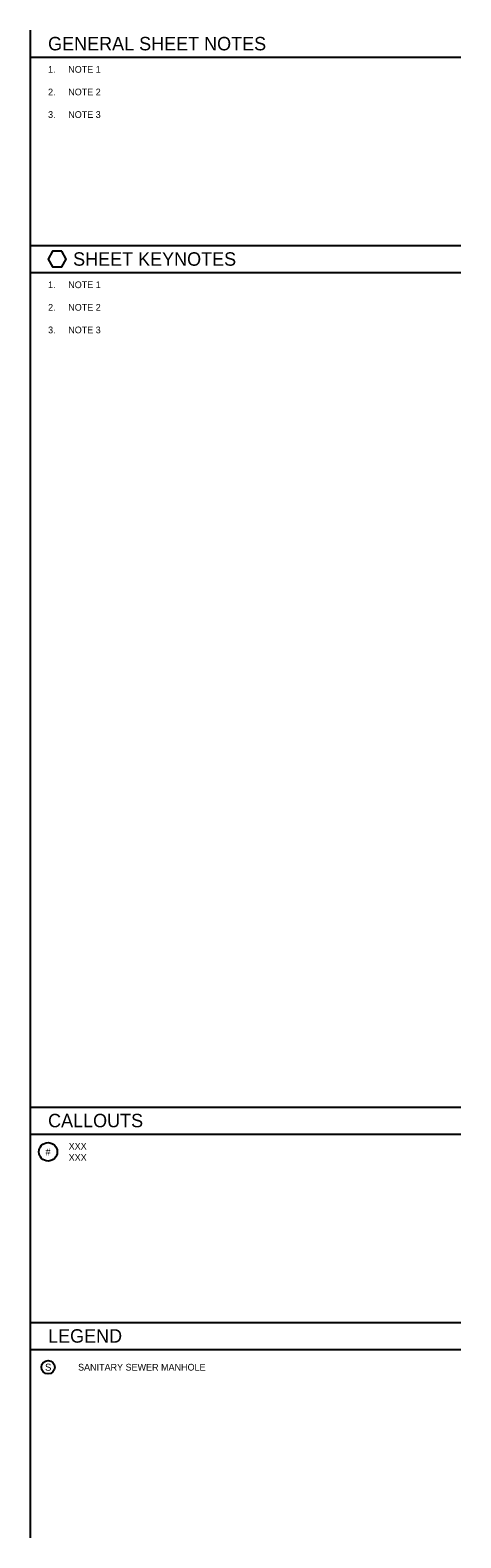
# Model space of a CAD drawing. Extents: x 2.11 to 2.61, y 0.03 to 1.78.
import ezdxf

# ---------------------------------------------------------------- set-up
doc = ezdxf.new("R2010")
doc.units = 0
for name, color, linetype in [('G-ANNO-KEYN', 7, 'Continuous'), ('G-ANNO-SYMB', 7, 'Continuous'), ('G-ANNO-TEXT', 7, 'Continuous'), ('G-DETL-GRPH', 7, 'Continuous')]:
    doc.layers.add(name, color=color, linetype=linetype)

msp = doc.modelspace()

# ---------------------------------------------------------------- linework, layer by layer
at = {"layer": 'G-ANNO-KEYN'}
msp.add_lwpolyline([(2.1512, 1.5273), (2.1407, 1.5273), (2.1354, 1.5182), (2.1407, 1.5091), (2.1512, 1.5091), (2.1565, 1.5182)], close=True, dxfattribs=at)
at = {"layer": 'G-ANNO-SYMB'}
for centre, radius in [((2.1354, 0.4819), 0.0107), ((2.1354, 0.2319), 0.00781)]:
    msp.add_circle(centre, radius, dxfattribs=at)
at = {"layer": 'G-DETL-GRPH'}
for p, q in [((2.1146, 1.7839), (2.1146, 0.0339)), ((2.1146, 1.7526), (2.6146, 1.7526)), ((2.1146, 1.5339), (2.6146, 1.5339)), ((2.1146, 1.5026), (2.6146, 1.5026)), ((2.1146, 0.5339), (2.6146, 0.5339)), ((2.1146, 0.5026), (2.6146, 0.5026)), ((2.1146, 0.2839), (2.6146, 0.2839)), ((2.1146, 0.2526), (2.6146, 0.2526))]:
    msp.add_line(p, q, dxfattribs=at)

# ---------------------------------------------------------------- texts
at = {"layer": 'G-ANNO-KEYN'}
for s, height, p in [('     SHEET KEYNOTES', 0.015625, (2.1354, 1.5104)), ('1.', 0.00781, (2.1354, 1.4844)), ('NOTE 1', 0.00781, (2.1588, 1.4844)), ('2.', 0.00781, (2.1354, 1.4582)), ('NOTE 2', 0.00781, (2.1588, 1.4582)), ('3.', 0.00781, (2.1354, 1.432)), ('NOTE 3', 0.00781, (2.1588, 1.432))]:
    msp.add_text(s, height=height, dxfattribs=at).set_placement(p)
at = {"layer": 'G-ANNO-SYMB'}
for s, height, p in [('#', 0.00781, (2.1324, 0.478)), ('S', 0.0082, (2.1319, 0.2278))]:
    msp.add_text(s, height=height, dxfattribs=at).set_placement(p)
at = {"layer": 'G-ANNO-TEXT'}
for s, height, p in [('GENERAL SHEET NOTES', 0.015625, (2.1354, 1.7604)), ('1.', 0.00781, (2.1354, 1.7344)), ('NOTE 1', 0.00781, (2.1588, 1.7344)), ('2.', 0.00781, (2.1354, 1.7082)), ('NOTE 2', 0.00781, (2.1588, 1.7082)), ('3.', 0.00781, (2.1354, 1.682)), ('NOTE 3', 0.00781, (2.1588, 1.682)), ('CALLOUTS', 0.01562, (2.1354, 0.5104)), ('XXX', 0.00781, (2.1593, 0.4845)), ('XXX', 0.00781, (2.1593, 0.4715)), ('LEGEND', 0.01562, (2.1354, 0.2604)), ('SANITARY SEWER MANHOLE', 0.007812, (2.1702, 0.228))]:
    msp.add_text(s, height=height, dxfattribs=at).set_placement(p)

doc.saveas('drawing.dxf')
